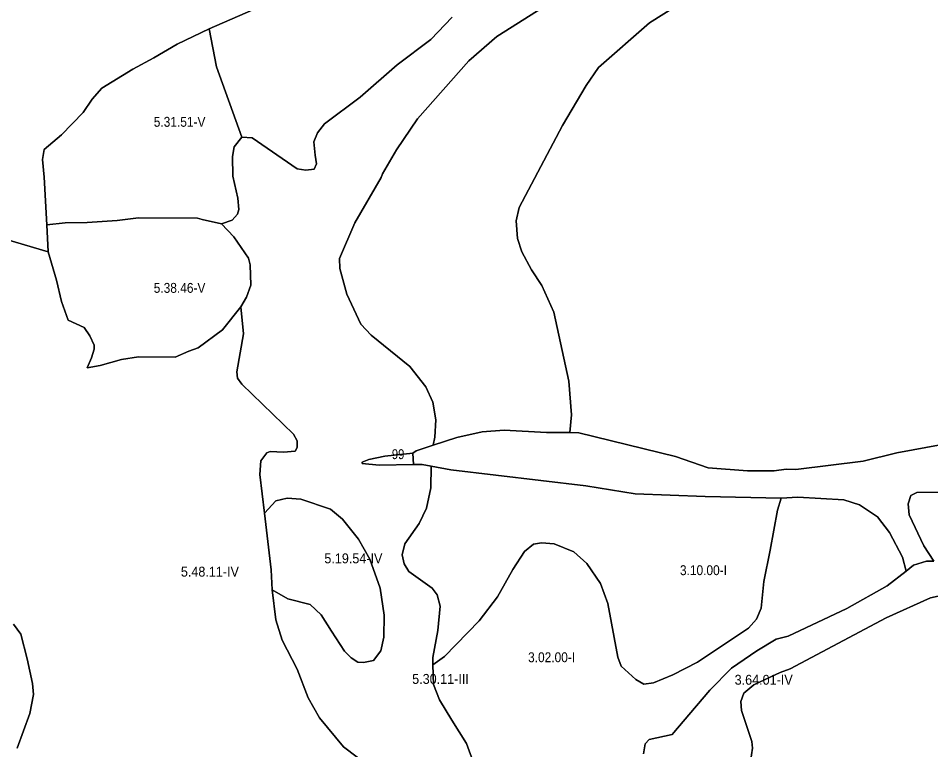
# Model space of a CAD drawing. Extents: x -591496 to -585489, y -1120610 to -1115685.
# Drawn here: x -589052 to -587209, y -1119158 to -1117681 of the extents above; entities that cross this region are included whole.
import ezdxf

# ---------------------------------------------------------------- set-up
doc = ezdxf.new("R2010")
doc.units = 0
doc.header["$LTSCALE"] = 8
doc.layers.add('40', color=7, linetype='Continuous', lineweight=25)
doc.layers.add('41', color=7, linetype='Continuous')

msp = doc.modelspace()

# ---------------------------------------------------------------- linework, layer by layer
at = {"layer": '40'}
for points in [[(-587684.5, -1117632), (-587777, -1117690.5), (-587880, -1117780.5), (-587904.5, -1117817), (-587952.5, -1117898), (-588040, -1118063), (-588046, -1118090), (-588043.5, -1118126), (-588034.5, -1118153), (-588015, -1118189)], [(-588040, -1118063), (-587952.5, -1117898), (-587904.5, -1117817), (-587880, -1117780.5), (-587777, -1117690.5), (-587684.5, -1117632)], [(-588015, -1118189), (-587994, -1118220.5), (-587970, -1118274.5), (-587939.5, -1118414), (-587934.5, -1118481.5), (-587937.5, -1118517.5), (-587984.5, -1118517.5), (-588070, -1118512.5), (-588114.5, -1118516), (-588165.5, -1118527.5), (-588213.5, -1118543), (-588210.5, -1118527), (-588208, -1118492), (-588214.5, -1118456), (-588228.5, -1118425.5), (-588261, -1118384), (-588339, -1118321), (-588359.5, -1118298.5), (-588388, -1118238), (-588402, -1118186.5), (-588403, -1118166), (-588371.5, -1118094), (-588318.5, -1118002.5), (-588316, -1117995.5), (-588287.5, -1117946.5), (-588245, -1117884.5), (-588141.5, -1117767), (-588085, -1117718), (-587964.5, -1117641.5)], [(-587964.5, -1117641.5), (-588085, -1117718), (-588141.5, -1117767), (-588245, -1117884.5), (-588287.5, -1117946.5), (-588316, -1117995.5), (-588318.5, -1118002.5), (-588371.5, -1118094), (-588403, -1118166), (-588402, -1118186.5), (-588388, -1118238), (-588359.5, -1118298.5), (-588339, -1118321), (-588261, -1118384), (-588228.5, -1118425.5), (-588214.5, -1118456), (-588208, -1118492), (-588210.5, -1118527), (-588213.5, -1118543), (-588248, -1118554.5), (-588254.5, -1118559), (-588311.5, -1118565), (-588343.5, -1118572), (-588357, -1118577.5), (-588357, -1118580), (-588323, -1118583.5), (-588253.508, -1118582.302), (-588236, -1118582), (-588217.984, -1118585.417), (-588218, -1118629.5), (-588227, -1118670), (-588242, -1118701.5), (-588271, -1118742), (-588276.5, -1118764.5), (-588272.5, -1118782.5), (-588263, -1118798), (-588215.5, -1118832), (-588205.5, -1118845.5), (-588199.5, -1118868), (-588204, -1118917.5), (-588214, -1118971.5), (-588214.5, -1118986.5), (-588213, -1119026), (-588200.5, -1119057.5), (-588176, -1119098), (-588146, -1119145.5), (-588131, -1119188)], [(-588578, -1117664), (-588666, -1117702.5), (-588730.5, -1117733.5), (-588777.5, -1117761), (-588820, -1117784), (-588882.5, -1117822), (-588902, -1117844.5), (-588920.5, -1117871.5), (-588964, -1117916.5), (-588999.5, -1117946), (-589002.5, -1117966), (-588999, -1118002), (-588994, -1118098), (-588991, -1118153), (-589112.5, -1118117)], [(-588175.5, -1117679), (-588218.5, -1117724), (-588286, -1117775.5), (-588361, -1117840.5), (-588433, -1117894.5), (-588447.5, -1117912.5), (-588454.5, -1117930.5), (-588452, -1117957.5), (-588449, -1117975), (-588454, -1117986), (-588471, -1117988), (-588488, -1117985), (-588579, -1117922.5), (-588600, -1117921), (-588651, -1117779.5), (-588666, -1117702.5), (-588578, -1117664)], [(-588379.5, -1118972.5), (-588365.5, -1118981), (-588354, -1118982), (-588334, -1118978), (-588319.5, -1118958), (-588313, -1118931), (-588312.5, -1118886), (-588320.5, -1118832), (-588341.5, -1118773.5), (-588364.5, -1118733), (-588396.5, -1118692.5), (-588421, -1118672), (-588481, -1118652), (-588508.5, -1118650), (-588531.5, -1118655.5), (-588554.202, -1118680.024), (-588563.5, -1118602), (-588561.5, -1118575), (-588549.5, -1118558.5), (-588543, -1118556), (-588516, -1118557), (-588492, -1118555), (-588488, -1118548), (-588488.5, -1118534.5), (-588496, -1118521), (-588600, -1118420), (-588608.5, -1118407.5), (-588610, -1118395), (-588596.5, -1118318.5), (-588602, -1118263.5), (-588590.5, -1118244.5), (-588582, -1118220), (-588583, -1118179), (-588586.5, -1118165.5), (-588616, -1118122.5), (-588641, -1118096), (-588619.5, -1118088.5), (-588609, -1118076.5), (-588606, -1118067), (-588608, -1118044.5), (-588618, -1118000), (-588619, -1117960.5), (-588615.5, -1117941), (-588600, -1117921), (-588579, -1117922.5), (-588488, -1117985), (-588471, -1117988), (-588454, -1117986), (-588449, -1117975), (-588452, -1117957.5), (-588454.5, -1117930.5), (-588447.5, -1117912.5), (-588433, -1117894.5), (-588361, -1117840.5), (-588286, -1117775.5), (-588218.5, -1117724), (-588175.5, -1117679)], [(-587186, -1118541.5), (-587277, -1118558.5), (-587345, -1118575.5), (-587481, -1118592.5), (-587500.5, -1118591.5), (-587525, -1118595), (-587578.5, -1118595), (-587658.5, -1118589), (-587724, -1118566), (-587919.5, -1118518.5), (-587937.5, -1118517.5), (-587934.5, -1118481.5), (-587939.5, -1118414), (-587970, -1118274.5), (-587994, -1118220.5), (-588015, -1118189), (-588034.5, -1118153), (-588043.5, -1118126), (-588046, -1118090), (-588040, -1118063)], [(-589290, -1118634), (-589281, -1118577), (-589282.5, -1118562), (-589279.5, -1118521.5), (-589272, -1118492), (-589247, -1118438), (-589238.5, -1118432.5), (-589204.5, -1118419.5), (-589102, -1118399.5), (-589104.5, -1118370.5), (-589110.5, -1118357), (-589137, -1118321), (-589152.5, -1118302.5), (-589170, -1118298.5), (-589199, -1118296.5), (-589226.5, -1118231), (-589243.5, -1118126), (-589247, -1118095), (-589227, -1118089), (-589210, -1118087), (-589133, -1118108.5), (-589112.5, -1118117), (-588991, -1118153)], [(-588991, -1118153), (-588974.5, -1118210), (-588964.5, -1118253), (-588950.5, -1118290.5), (-588918.5, -1118305.5), (-588907, -1118322), (-588898.5, -1118341), (-588898, -1118349), (-588903.5, -1118367), (-588912.5, -1118387), (-588886, -1118382), (-588843, -1118370), (-588808.5, -1118365), (-588735, -1118365.5), (-588707, -1118353), (-588688, -1118346.5), (-588639, -1118310), (-588602, -1118263.5), (-588596.5, -1118318.5), (-588610, -1118395), (-588608.5, -1118407.5), (-588600, -1118420), (-588496, -1118521), (-588488.5, -1118534.5), (-588488, -1118548), (-588492, -1118555), (-588516, -1118557), (-588543, -1118556), (-588549.5, -1118558.5), (-588561.5, -1118575), (-588563.5, -1118602), (-588554.202, -1118680.024), (-588540.5, -1118795), (-588538.5, -1118835), (-588531.5, -1118896), (-588518.5, -1118936.5), (-588488, -1118995), (-588466, -1119053.5), (-588443.5, -1119093.5), (-588395, -1119152), (-588317, -1119211)], [(-587193, -1118638), (-587237, -1118638.5), (-587249, -1118644.5), (-587254.5, -1118661.5), (-587252, -1118684), (-587222.5, -1118746.5), (-587202.5, -1118777), (-587217, -1118777.5), (-587243.5, -1118785.5), (-587258.381, -1118797.152), (-587266, -1118769), (-587292, -1118719.5), (-587316.5, -1118688), (-587352.5, -1118663.5), (-587384, -1118653.5), (-587477, -1118648), (-587511, -1118650), (-587664.5, -1118646.5), (-587806, -1118641.5), (-587905, -1118625), (-588178, -1118593), (-588217.984, -1118585.417), (-588236, -1118582), (-588253.508, -1118582.302), (-588254.5, -1118559), (-588248, -1118554.5), (-588213.5, -1118543), (-588165.5, -1118527.5), (-588114.5, -1118516), (-588070, -1118512.5), (-587984.5, -1118517.5), (-587937.5, -1118517.5), (-587919.5, -1118518.5), (-587724, -1118566), (-587658.5, -1118589), (-587578.5, -1118595), (-587525, -1118595), (-587500.5, -1118591.5), (-587481, -1118592.5), (-587345, -1118575.5), (-587277, -1118558.5), (-587186, -1118541.5)], [(-587202.5, -1118777), (-587222.5, -1118746.5), (-587252, -1118684), (-587254.5, -1118661.5), (-587249, -1118644.5), (-587237, -1118638.5), (-587193, -1118638)], [(-588131, -1119188), (-588146, -1119145.5), (-588176, -1119098), (-588200.5, -1119057.5), (-588213, -1119026), (-588214.5, -1118986.5), (-588190.5, -1118970), (-588120.5, -1118898), (-588083.5, -1118849.5), (-588053, -1118794), (-588029.5, -1118758), (-588011, -1118743), (-587995, -1118740), (-587969, -1118742.5), (-587929.5, -1118758.5), (-587903, -1118782), (-587875.5, -1118822.5), (-587861, -1118863), (-587841, -1118971), (-587834, -1118989), (-587804, -1119016), (-587788.5, -1119025.5), (-587768.5, -1119023), (-587729.5, -1119006.5), (-587679.5, -1118981.5), (-587576.5, -1118912.5), (-587560.5, -1118894.5), (-587551.5, -1118872), (-587546, -1118818), (-587533, -1118755), (-587518.5, -1118674), (-587511, -1118650), (-587477, -1118648), (-587384, -1118653.5), (-587352.5, -1118663.5), (-587316.5, -1118688), (-587292, -1118719.5), (-587266, -1118769), (-587258.381, -1118797.152), (-587296.5, -1118827), (-587378, -1118873), (-587497, -1118928.5), (-587521, -1118935), (-587560, -1118958), (-587611, -1118993), (-587655, -1119038), (-587709, -1119101), (-587727.5, -1119123.5), (-587731, -1119127), (-587777.5, -1119137), (-587785.5, -1119146), (-587789, -1119166.5)], [(-587789, -1119166.5), (-587785.5, -1119146), (-587777.5, -1119137), (-587731, -1119127), (-587727.5, -1119123.5), (-587709, -1119101), (-587655, -1119038), (-587611, -1118993), (-587560, -1118958), (-587521, -1118935), (-587497, -1118928.5), (-587378, -1118873), (-587296.5, -1118827), (-587258.381, -1118797.152), (-587243.5, -1118785.5), (-587217, -1118777.5), (-587202.5, -1118777)], [(-588317, -1119211), (-588395, -1119152), (-588443.5, -1119093.5), (-588466, -1119053.5), (-588488, -1118995), (-588518.5, -1118936.5), (-588531.5, -1118896), (-588538.5, -1118835), (-588507, -1118853), (-588462, -1118865), (-588439.5, -1118885.5), (-588419, -1118918.5), (-588392.5, -1118959), (-588379.5, -1118972.5)], [(-587572.5, -1119182), (-587569, -1119155), (-587570, -1119141.5), (-587591, -1119078.5), (-587592.5, -1119060.5), (-587586.5, -1119043.5), (-587566, -1119027), (-587512.5, -1119002), (-587492.5, -1118994.5), (-587298.5, -1118892), (-587209.5, -1118851.5), (-587188, -1118846.5)], [(-587188, -1118846.5), (-587209.5, -1118851.5), (-587298.5, -1118892), (-587492.5, -1118994.5), (-587512.5, -1119002), (-587566, -1119027), (-587586.5, -1119043.5), (-587592.5, -1119060.5), (-587591, -1119078.5), (-587570, -1119141.5), (-587569, -1119155), (-587572.5, -1119182)], [(-589061.5, -1118904.5), (-589046.5, -1118924.5), (-589033.5, -1118974.5), (-589022.5, -1119024), (-589021, -1119046.5), (-589028.5, -1119084.5), (-589053.5, -1119154.5)], [(-589053.5, -1119154.5), (-589028.5, -1119084.5), (-589021, -1119046.5), (-589022.5, -1119024), (-589033.5, -1118974.5), (-589046.5, -1118924.5), (-589061.5, -1118904.5)]]:
    msp.add_lwpolyline(points, dxfattribs=at)
for points in [[(-588600, -1117921), (-588615.5, -1117941), (-588619, -1117960.5), (-588618, -1118000), (-588608, -1118044.5), (-588606, -1118067), (-588609, -1118076.5), (-588619.5, -1118088.5), (-588641, -1118096), (-588680, -1118087.5), (-588689.5, -1118084.5), (-588809, -1118084), (-588851.5, -1118089.5), (-588912.5, -1118093.5), (-588957, -1118094.5), (-588994, -1118098), (-588999, -1118002), (-589002.5, -1117966), (-588999.5, -1117946), (-588964, -1117916.5), (-588920.5, -1117871.5), (-588902, -1117844.5), (-588882.5, -1117822), (-588820, -1117784), (-588777.5, -1117761), (-588730.5, -1117733.5), (-588666, -1117702.5), (-588651, -1117779.5)], [(-588641, -1118096), (-588616, -1118122.5), (-588586.5, -1118165.5), (-588583, -1118179), (-588582, -1118220), (-588590.5, -1118244.5), (-588602, -1118263.5), (-588639, -1118310), (-588688, -1118346.5), (-588707, -1118353), (-588735, -1118365.5), (-588808.5, -1118365), (-588843, -1118370), (-588886, -1118382), (-588912.5, -1118387), (-588903.5, -1118367), (-588898, -1118349), (-588898.5, -1118341), (-588907, -1118322), (-588918.5, -1118305.5), (-588950.5, -1118290.5), (-588964.5, -1118253), (-588974.5, -1118210), (-588991, -1118153), (-588994, -1118098), (-588957, -1118094.5), (-588912.5, -1118093.5), (-588851.5, -1118089.5), (-588809, -1118084), (-588689.5, -1118084.5), (-588680, -1118087.5)], [(-588253.508, -1118582.302), (-588323, -1118583.5), (-588357, -1118580), (-588357, -1118577.5), (-588343.5, -1118572), (-588311.5, -1118565), (-588254.5, -1118559)], [(-587511, -1118650), (-587518.5, -1118674), (-587533, -1118755), (-587546, -1118818), (-587551.5, -1118872), (-587560.5, -1118894.5), (-587576.5, -1118912.5), (-587679.5, -1118981.5), (-587729.5, -1119006.5), (-587768.5, -1119023), (-587788.5, -1119025.5), (-587804, -1119016), (-587834, -1118989), (-587841, -1118971), (-587861, -1118863), (-587875.5, -1118822.5), (-587903, -1118782), (-587929.5, -1118758.5), (-587969, -1118742.5), (-587995, -1118740), (-588011, -1118743), (-588029.5, -1118758), (-588053, -1118794), (-588083.5, -1118849.5), (-588120.5, -1118898), (-588190.5, -1118970), (-588214.5, -1118986.5), (-588214, -1118971.5), (-588204, -1118917.5), (-588199.5, -1118868), (-588205.5, -1118845.5), (-588215.5, -1118832), (-588263, -1118798), (-588272.5, -1118782.5), (-588276.5, -1118764.5), (-588271, -1118742), (-588242, -1118701.5), (-588227, -1118670), (-588218, -1118629.5), (-588217.984, -1118585.417), (-588178, -1118593), (-587905, -1118625), (-587806, -1118641.5), (-587664.5, -1118646.5)], [(-588538.5, -1118835), (-588540.5, -1118795), (-588554.202, -1118680.024), (-588531.5, -1118655.5), (-588508.5, -1118650), (-588481, -1118652), (-588421, -1118672), (-588396.5, -1118692.5), (-588364.5, -1118733), (-588341.5, -1118773.5), (-588320.5, -1118832), (-588312.5, -1118886), (-588313, -1118931), (-588319.5, -1118958), (-588334, -1118978), (-588354, -1118982), (-588365.5, -1118981), (-588379.5, -1118972.5), (-588392.5, -1118959), (-588419, -1118918.5), (-588439.5, -1118885.5), (-588462, -1118865), (-588507, -1118853)]]:
    msp.add_lwpolyline(points, close=True, dxfattribs=at)

# ---------------------------------------------------------------- texts
at = {"layer": '41'}
for s, width, p in [('5.31.51-V', 0.9, (-588777.906, -1117900.25)), ('5.38.46-V', 0.9, (-588777.969, -1118235.5)), ('99', 0.85, (-588297.031, -1118571.25)), ('5.19.54-IV', 0.95, (-588433.375, -1118781.625)), ('5.48.11-IV', 0.95, (-588723.125, -1118808.438)), ('3.10.00-I', 0.9, (-587715.25, -1118805.5)), ('3.02.00-I', 0.9, (-588021.938, -1118981.25)), ('5.30.11-III', 0.95, (-588256, -1119025)), ('3.64.01-IV', 0.95, (-587604.75, -1119026.75))]:
    msp.add_text(s, height=20, dxfattribs=dict(at, width=width)).set_placement(p)

doc.saveas('drawing.dxf')
